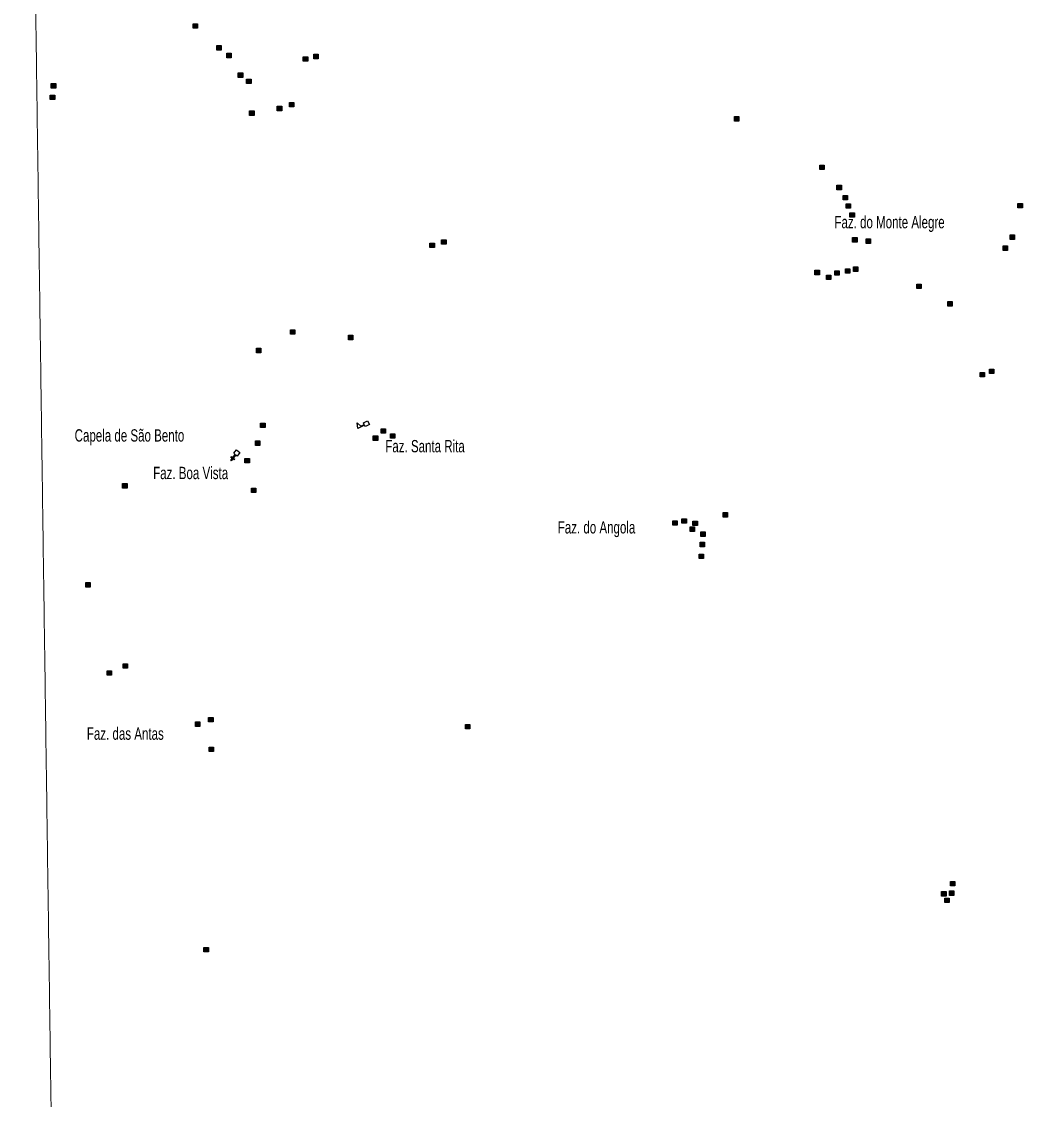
# Model space of a CAD drawing. Extents: x 265.7 to 292.1, y 7676.2 to 7704.2.
# Drawn here: x 265.72 to 272.22, y 7690.19 to 7697.19 of the extents above; entities that cross this region are included whole.
import ezdxf

# ---------------------------------------------------------------- set-up
doc = ezdxf.new("R2010")
doc.units = 0
doc.header["$LTSCALE"] = 0.032
for name, color, linetype, lineweight in [('2', 7, 'Continuous', 25), ('4', 7, 'Continuous', 25), ('6', 7, 'Continuous', 25), ('63', 7, 'Continuous', 13)]:
    doc.layers.add(name, color=color, linetype=linetype, lineweight=lineweight)
doc.layers.add('61', color=7, linetype='Continuous')

msp = doc.modelspace()

# ---------------------------------------------------------------- hatches: boundary and pattern name
at = {"layer": '2'}
for points in [[(266.8317, 7697.1783), (266.8607, 7697.1783), (266.8607, 7697.1493), (266.8317, 7697.1493)], [(266.9858, 7697.0362), (267.0148, 7697.0362), (267.0148, 7697.0072), (266.9858, 7697.0072)], [(267.0511, 7696.9861), (267.0801, 7696.9861), (267.0801, 7696.9571), (267.0511, 7696.9571)], [(267.5475, 7696.9635), (267.5765, 7696.9635), (267.5765, 7696.9345), (267.5475, 7696.9345)], [(267.6162, 7696.9796), (267.6452, 7696.9796), (267.6452, 7696.9506), (267.6162, 7696.9506)], [(267.1255, 7696.8586), (267.1545, 7696.8586), (267.1545, 7696.8296), (267.1255, 7696.8296)], [(265.9108, 7696.7892), (265.9398, 7696.7892), (265.9398, 7696.7602), (265.9108, 7696.7602)], [(267.1796, 7696.8191), (267.2086, 7696.8191), (267.2086, 7696.7901), (267.1796, 7696.7901)], [(265.9045, 7696.715), (265.9335, 7696.715), (265.9335, 7696.686), (265.9045, 7696.686)], [(267.3788, 7696.6423), (267.4078, 7696.6423), (267.4078, 7696.6133), (267.3788, 7696.6133)], [(267.4571, 7696.6674), (267.4861, 7696.6674), (267.4861, 7696.6384), (267.4571, 7696.6384)], [(267.1989, 7696.6116), (267.2279, 7696.6116), (267.2279, 7696.5826), (267.1989, 7696.5826)], [(270.3479, 7696.5754), (270.3769, 7696.5754), (270.3769, 7696.5464), (270.3479, 7696.5464)], [(270.9025, 7696.2598), (270.9315, 7696.2598), (270.9315, 7696.2308), (270.9025, 7696.2308)], [(271.0138, 7696.1291), (271.0428, 7696.1291), (271.0428, 7696.1001), (271.0138, 7696.1001)], [(271.0541, 7696.063), (271.0831, 7696.063), (271.0831, 7696.034), (271.0541, 7696.034)], [(271.0734, 7696.0088), (271.1024, 7696.0088), (271.1024, 7695.9798), (271.0734, 7695.9798)], [(271.0986, 7695.95), (271.1276, 7695.95), (271.1276, 7695.921), (271.0986, 7695.921)], [(272.1896, 7696.0112), (272.2186, 7696.0112), (272.2186, 7695.9822), (272.1896, 7695.9822)], [(272.139, 7695.8063), (272.168, 7695.8063), (272.168, 7695.7773), (272.139, 7695.7773)], [(268.3707, 7695.7529), (268.3997, 7695.7529), (268.3997, 7695.7239), (268.3707, 7695.7239)], [(268.4458, 7695.7755), (268.4748, 7695.7755), (268.4748, 7695.7465), (268.4458, 7695.7465)], [(271.1156, 7695.7886), (271.1446, 7695.7886), (271.1446, 7695.7596), (271.1156, 7695.7596)], [(271.2027, 7695.7804), (271.2317, 7695.7804), (271.2317, 7695.7514), (271.2027, 7695.7514)], [(272.0929, 7695.7353), (272.1219, 7695.7353), (272.1219, 7695.7063), (272.0929, 7695.7063)], [(271.1203, 7695.5988), (271.1493, 7695.5988), (271.1493, 7695.5698), (271.1203, 7695.5698)], [(270.871, 7695.5771), (270.9, 7695.5771), (270.9, 7695.5481), (270.871, 7695.5481)], [(270.946, 7695.5456), (270.975, 7695.5456), (270.975, 7695.5166), (270.946, 7695.5166)], [(271.0001, 7695.5739), (271.0291, 7695.5739), (271.0291, 7695.5449), (271.0001, 7695.5449)], [(271.0695, 7695.5868), (271.0985, 7695.5868), (271.0985, 7695.5578), (271.0695, 7695.5578)], [(271.5328, 7695.4867), (271.5618, 7695.4867), (271.5618, 7695.4577), (271.5328, 7695.4577)], [(271.7337, 7695.3737), (271.7627, 7695.3737), (271.7627, 7695.3447), (271.7337, 7695.3447)], [(267.4645, 7695.1906), (267.4935, 7695.1906), (267.4935, 7695.1616), (267.4645, 7695.1616)], [(267.8405, 7695.1542), (267.8695, 7695.1542), (267.8695, 7695.1252), (267.8405, 7695.1252)], [(267.2433, 7695.0702), (267.2723, 7695.0702), (267.2723, 7695.0412), (267.2433, 7695.0412)], [(271.9436, 7694.9137), (271.9726, 7694.9137), (271.9726, 7694.8847), (271.9436, 7694.8847)], [(272.0047, 7694.9348), (272.0337, 7694.9348), (272.0337, 7694.9058), (272.0047, 7694.9058)], [(267.2708, 7694.5844), (267.2998, 7694.5844), (267.2998, 7694.5554), (267.2708, 7694.5554)], [(268.0528, 7694.5473), (268.0818, 7694.5473), (268.0818, 7694.5183), (268.0528, 7694.5183)], [(268.0019, 7694.5004), (268.0309, 7694.5004), (268.0309, 7694.4714), (268.0019, 7694.4714)], [(268.1141, 7694.515), (268.1431, 7694.515), (268.1431, 7694.486), (268.1141, 7694.486)], [(267.2363, 7694.468), (267.2653, 7694.468), (267.2653, 7694.439), (267.2363, 7694.439)], [(267.169, 7694.3543), (267.198, 7694.3543), (267.198, 7694.3253), (267.169, 7694.3253)], [(266.374, 7694.1913), (266.403, 7694.1913), (266.403, 7694.1623), (266.374, 7694.1623)], [(267.211, 7694.1615), (267.24, 7694.1615), (267.24, 7694.1325), (267.211, 7694.1325)], [(270.2745, 7694.0025), (270.3035, 7694.0025), (270.3035, 7693.9735), (270.2745, 7693.9735)], [(269.9477, 7693.9493), (269.9767, 7693.9493), (269.9767, 7693.9203), (269.9477, 7693.9203)], [(270.0074, 7693.963), (270.0364, 7693.963), (270.0364, 7693.934), (270.0074, 7693.934)], [(270.0784, 7693.9477), (270.1074, 7693.9477), (270.1074, 7693.9187), (270.0784, 7693.9187)], [(270.0607, 7693.9097), (270.0897, 7693.9097), (270.0897, 7693.8807), (270.0607, 7693.8807)], [(270.1293, 7693.8774), (270.1583, 7693.8774), (270.1583, 7693.8484), (270.1293, 7693.8484)], [(270.1244, 7693.8096), (270.1534, 7693.8096), (270.1534, 7693.7806), (270.1244, 7693.7806)], [(270.1189, 7693.7337), (270.1479, 7693.7337), (270.1479, 7693.7047), (270.1189, 7693.7047)], [(266.1352, 7693.5482), (266.1642, 7693.5482), (266.1642, 7693.5192), (266.1352, 7693.5192)], [(266.3773, 7693.0212), (266.4063, 7693.0212), (266.4063, 7692.9922), (266.3773, 7692.9922)], [(266.2732, 7692.9752), (266.3022, 7692.9752), (266.3022, 7692.9462), (266.2732, 7692.9462)], [(266.9326, 7692.6717), (266.9616, 7692.6717), (266.9616, 7692.6427), (266.9326, 7692.6427)], [(266.847, 7692.6426), (266.876, 7692.6426), (266.876, 7692.6136), (266.847, 7692.6136)], [(268.6008, 7692.6265), (268.6298, 7692.6265), (268.6298, 7692.5975), (268.6008, 7692.5975)], [(266.9366, 7692.4797), (266.9656, 7692.4797), (266.9656, 7692.4507), (266.9366, 7692.4507)], [(271.7507, 7691.6071), (271.7797, 7691.6071), (271.7797, 7691.5781), (271.7507, 7691.5781)], [(271.6935, 7691.541), (271.7225, 7691.541), (271.7225, 7691.512), (271.6935, 7691.512)], [(271.7442, 7691.545), (271.7732, 7691.545), (271.7732, 7691.516), (271.7442, 7691.516)], [(271.7136, 7691.4983), (271.7426, 7691.4983), (271.7426, 7691.4693), (271.7136, 7691.4693)], [(266.9027, 7691.1787), (266.9317, 7691.1787), (266.9317, 7691.1497), (266.9027, 7691.1497)]]:
    msp.add_hatch(color=256, dxfattribs=at).paths.add_polyline_path(points)

# ---------------------------------------------------------------- linework, layer by layer
for points in [[(266.8317, 7697.1783), (266.8607, 7697.1783), (266.8607, 7697.1493), (266.8317, 7697.1493)], [(266.9858, 7697.0362), (267.0148, 7697.0362), (267.0148, 7697.0072), (266.9858, 7697.0072)], [(267.0511, 7696.9861), (267.0801, 7696.9861), (267.0801, 7696.9571), (267.0511, 7696.9571)], [(267.5475, 7696.9635), (267.5765, 7696.9635), (267.5765, 7696.9345), (267.5475, 7696.9345)], [(267.6162, 7696.9796), (267.6452, 7696.9796), (267.6452, 7696.9506), (267.6162, 7696.9506)], [(267.1255, 7696.8586), (267.1545, 7696.8586), (267.1545, 7696.8296), (267.1255, 7696.8296)], [(265.9108, 7696.7892), (265.9398, 7696.7892), (265.9398, 7696.7602), (265.9108, 7696.7602)], [(267.1796, 7696.8191), (267.2086, 7696.8191), (267.2086, 7696.7901), (267.1796, 7696.7901)], [(265.9045, 7696.715), (265.9335, 7696.715), (265.9335, 7696.686), (265.9045, 7696.686)], [(267.3788, 7696.6423), (267.4078, 7696.6423), (267.4078, 7696.6133), (267.3788, 7696.6133)], [(267.4571, 7696.6674), (267.4861, 7696.6674), (267.4861, 7696.6384), (267.4571, 7696.6384)], [(267.1989, 7696.6116), (267.2279, 7696.6116), (267.2279, 7696.5826), (267.1989, 7696.5826)], [(270.3479, 7696.5754), (270.3769, 7696.5754), (270.3769, 7696.5464), (270.3479, 7696.5464)], [(270.9025, 7696.2598), (270.9315, 7696.2598), (270.9315, 7696.2308), (270.9025, 7696.2308)], [(271.0138, 7696.1291), (271.0428, 7696.1291), (271.0428, 7696.1001), (271.0138, 7696.1001)], [(271.0541, 7696.063), (271.0831, 7696.063), (271.0831, 7696.034), (271.0541, 7696.034)], [(271.0734, 7696.0088), (271.1024, 7696.0088), (271.1024, 7695.9798), (271.0734, 7695.9798)], [(271.0986, 7695.95), (271.1276, 7695.95), (271.1276, 7695.921), (271.0986, 7695.921)], [(272.1896, 7696.0112), (272.2186, 7696.0112), (272.2186, 7695.9822), (272.1896, 7695.9822)], [(272.139, 7695.8063), (272.168, 7695.8063), (272.168, 7695.7773), (272.139, 7695.7773)], [(268.3707, 7695.7529), (268.3997, 7695.7529), (268.3997, 7695.7239), (268.3707, 7695.7239)], [(268.4458, 7695.7755), (268.4748, 7695.7755), (268.4748, 7695.7465), (268.4458, 7695.7465)], [(271.1156, 7695.7886), (271.1446, 7695.7886), (271.1446, 7695.7596), (271.1156, 7695.7596)], [(271.2027, 7695.7804), (271.2317, 7695.7804), (271.2317, 7695.7514), (271.2027, 7695.7514)], [(272.0929, 7695.7353), (272.1219, 7695.7353), (272.1219, 7695.7063), (272.0929, 7695.7063)], [(271.1203, 7695.5988), (271.1493, 7695.5988), (271.1493, 7695.5698), (271.1203, 7695.5698)], [(270.871, 7695.5771), (270.9, 7695.5771), (270.9, 7695.5481), (270.871, 7695.5481)], [(270.946, 7695.5456), (270.975, 7695.5456), (270.975, 7695.5166), (270.946, 7695.5166)], [(271.0001, 7695.5739), (271.0291, 7695.5739), (271.0291, 7695.5449), (271.0001, 7695.5449)], [(271.0695, 7695.5868), (271.0985, 7695.5868), (271.0985, 7695.5578), (271.0695, 7695.5578)], [(271.5328, 7695.4867), (271.5618, 7695.4867), (271.5618, 7695.4577), (271.5328, 7695.4577)], [(271.7337, 7695.3737), (271.7627, 7695.3737), (271.7627, 7695.3447), (271.7337, 7695.3447)], [(267.4645, 7695.1906), (267.4935, 7695.1906), (267.4935, 7695.1616), (267.4645, 7695.1616)], [(267.8405, 7695.1542), (267.8695, 7695.1542), (267.8695, 7695.1252), (267.8405, 7695.1252)], [(267.2433, 7695.0702), (267.2723, 7695.0702), (267.2723, 7695.0412), (267.2433, 7695.0412)], [(271.9436, 7694.9137), (271.9726, 7694.9137), (271.9726, 7694.8847), (271.9436, 7694.8847)], [(272.0047, 7694.9348), (272.0337, 7694.9348), (272.0337, 7694.9058), (272.0047, 7694.9058)], [(267.2708, 7694.5844), (267.2998, 7694.5844), (267.2998, 7694.5554), (267.2708, 7694.5554)], [(268.0528, 7694.5473), (268.0818, 7694.5473), (268.0818, 7694.5183), (268.0528, 7694.5183)], [(268.0019, 7694.5004), (268.0309, 7694.5004), (268.0309, 7694.4714), (268.0019, 7694.4714)], [(268.1141, 7694.515), (268.1431, 7694.515), (268.1431, 7694.486), (268.1141, 7694.486)], [(267.2363, 7694.468), (267.2653, 7694.468), (267.2653, 7694.439), (267.2363, 7694.439)], [(267.169, 7694.3543), (267.198, 7694.3543), (267.198, 7694.3253), (267.169, 7694.3253)], [(266.374, 7694.1913), (266.403, 7694.1913), (266.403, 7694.1623), (266.374, 7694.1623)], [(267.211, 7694.1615), (267.24, 7694.1615), (267.24, 7694.1325), (267.211, 7694.1325)], [(270.2745, 7694.0025), (270.3035, 7694.0025), (270.3035, 7693.9735), (270.2745, 7693.9735)], [(269.9477, 7693.9493), (269.9767, 7693.9493), (269.9767, 7693.9203), (269.9477, 7693.9203)], [(270.0074, 7693.963), (270.0364, 7693.963), (270.0364, 7693.934), (270.0074, 7693.934)], [(270.0784, 7693.9477), (270.1074, 7693.9477), (270.1074, 7693.9187), (270.0784, 7693.9187)], [(270.0607, 7693.9097), (270.0897, 7693.9097), (270.0897, 7693.8807), (270.0607, 7693.8807)], [(270.1293, 7693.8774), (270.1583, 7693.8774), (270.1583, 7693.8484), (270.1293, 7693.8484)], [(270.1244, 7693.8096), (270.1534, 7693.8096), (270.1534, 7693.7806), (270.1244, 7693.7806)], [(270.1189, 7693.7337), (270.1479, 7693.7337), (270.1479, 7693.7047), (270.1189, 7693.7047)], [(266.1352, 7693.5482), (266.1642, 7693.5482), (266.1642, 7693.5192), (266.1352, 7693.5192)], [(266.3773, 7693.0212), (266.4063, 7693.0212), (266.4063, 7692.9922), (266.3773, 7692.9922)], [(266.2732, 7692.9752), (266.3022, 7692.9752), (266.3022, 7692.9462), (266.2732, 7692.9462)], [(266.9326, 7692.6717), (266.9616, 7692.6717), (266.9616, 7692.6427), (266.9326, 7692.6427)], [(266.847, 7692.6426), (266.876, 7692.6426), (266.876, 7692.6136), (266.847, 7692.6136)], [(268.6008, 7692.6265), (268.6298, 7692.6265), (268.6298, 7692.5975), (268.6008, 7692.5975)], [(266.9366, 7692.4797), (266.9656, 7692.4797), (266.9656, 7692.4507), (266.9366, 7692.4507)], [(271.7507, 7691.6071), (271.7797, 7691.6071), (271.7797, 7691.5781), (271.7507, 7691.5781)], [(271.6935, 7691.541), (271.7225, 7691.541), (271.7225, 7691.512), (271.6935, 7691.512)], [(271.7442, 7691.545), (271.7732, 7691.545), (271.7732, 7691.516), (271.7442, 7691.516)], [(271.7136, 7691.4983), (271.7426, 7691.4983), (271.7426, 7691.4693), (271.7136, 7691.4693)], [(266.9027, 7691.1787), (266.9317, 7691.1787), (266.9317, 7691.1497), (266.9027, 7691.1497)]]:
    msp.add_lwpolyline(points, close=True, dxfattribs=at)
at = {"layer": '4'}
for points in [[(267.946, 7694.5716), (267.9027, 7694.5499), (267.8979, 7694.5854), (267.9205, 7694.5643), (267.9438, 7694.576)], [(267.9438, 7694.576), (267.9384, 7694.5868), (267.9643, 7694.5998), (267.9773, 7694.5739), (267.9514, 7694.5609), (267.946, 7694.5716)]]:
    msp.add_lwpolyline(points, dxfattribs=at)
at = {"layer": '6'}
for points in [[(267.1053, 7694.3805), (267.0957, 7694.3878), (267.1131, 7694.4109), (267.1363, 7694.3935), (267.1188, 7694.3703), (267.1091, 7694.3776)], [(267.1091, 7694.3776), (267.0929, 7694.3559), (267.1025, 7694.3487), (267.0996, 7694.3447), (267.0899, 7694.352), (267.08, 7694.339), (267.0762, 7694.3418), (267.086, 7694.3549), (267.0764, 7694.3622), (267.0793, 7694.3661), (267.089, 7694.3589), (267.1053, 7694.3805)]]:
    msp.add_lwpolyline(points, dxfattribs=at)
at = {"layer": '63'}
msp.add_spline([(266.1055, 7676.1764), (266.0976, 7676.7414), (266.0896, 7677.3064), (266.0817, 7677.8713), (266.0737, 7678.4363), (266.0658, 7679.0013), (266.0578, 7679.5663), (266.0499, 7680.1313), (266.0419, 7680.6963), (266.034, 7681.2613), (266.026, 7681.8263), (266.0181, 7682.3913), (266.0102, 7682.9563), (266.0022, 7683.5212), (265.9943, 7684.0862), (265.9864, 7684.6512), (265.9785, 7685.2162), (265.9705, 7685.7812), (265.9626, 7686.3462), (265.9547, 7686.9112), (265.9468, 7687.4762), (265.9389, 7688.0411), (265.9309, 7688.6061), (265.923, 7689.1711), (265.9151, 7689.7361), (265.9072, 7690.3011), (265.8993, 7690.8661), (265.8914, 7691.4311), (265.8835, 7691.996), (265.8756, 7692.561), (265.8677, 7693.126), (265.8598, 7693.691), (265.8519, 7694.256), (265.844, 7694.821), (265.8361, 7695.3859), (265.8282, 7695.9509), (265.8203, 7696.5159), (265.8124, 7697.0809), (265.8045, 7697.6459), (265.7967, 7698.2108), (265.7888, 7698.7758), (265.7809, 7699.3408), (265.773, 7699.9058), (265.7651, 7700.4708), (265.7573, 7701.0357), (265.7494, 7701.6007), (265.7415, 7702.1657), (265.7337, 7702.7307), (265.7258, 7703.2957), (265.7179, 7703.8606)], degree=3, dxfattribs=at)

# ---------------------------------------------------------------- texts
at = {"layer": '61', "width": 0.7}
for s, p in [('Faz. do Monte Alegre', (270.9975, 7695.8495)), ('Capela de São Bento', (266.0628, 7694.464)), ('Faz. Santa Rita', (268.0804, 7694.3942)), ('Faz. Boa Vista', (266.5727, 7694.2201)), ('Faz. do Angola', (269.2006, 7693.867)), ('Faz. das Antas', (266.1421, 7692.527))]:
    msp.add_text(s, height=0.08, dxfattribs=at).set_placement(p)

doc.saveas('drawing.dxf')
